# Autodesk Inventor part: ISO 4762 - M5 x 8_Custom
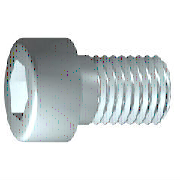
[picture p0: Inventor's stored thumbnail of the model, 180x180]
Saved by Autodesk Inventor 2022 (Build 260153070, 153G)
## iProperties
IsCustomPart: 0
Created: 2021-02
Part Number: ISO 4762 - M5 x 8_Custom
Material: Acier inoxydable 440C
Description: Vis cylindrique à six pans creux
Document SubType Name: Modeling
Standard: ISO 4762
Designer: Fabian
Standard Revision: Fourth edition 2004-03-01
Standards Organization: ISO
Language: fr-FR
Size Designation: M5 x 8
Categories: <MemberInstance><Categories><Category DisplayName="Visserie" InternalName="e4da775c-781d-43d5-af7c-5136215cf5a6" Mnemonic="FSTN"><Category DisplayName="Vis" Int
Density: 7.75 g/cm^3
Appearance: Semi-poli
Author: Fabian
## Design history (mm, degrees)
sketch "Esquisse1"
  geometry: L1 (-1.167, 0)-(8, 0); L2 (8, 0)-(8, 2.5); L3 (8, 2.5)-(2, 2.5); L4 (2, 2.5)-(1.509, 2.5); L5 (1.509, 2.5)-(0, 2.5); L6 (0, 2.5)-(0, 4.25); L7 (0, 4.25)-(-5, 4.25); L8 (-5, 4.25)-(-5, 2.309); L9 (-5, 2.309)-(-2.5, 2.309); L10 (-2.5, 2.309)-(-1.167, 0); L11 (-7.6, 0)-(10.6, 0) reference; L12 (0, -0.85)-(0, 5.1) reference; L13 (2, 2.5)-(0, 2.5)
  constraints: 22 end point, 6 parallel, 2 collinear, 2 perpendicular, 1 horizontal, 1 point on line
  dimensions: "d1" = 6 distance from line of L3.end L2 (= GEL); "d2" = 0.49086 distance of L4.end L3.end (computed from GAL); "d3" = 5 distance between parallel lines of L8 L6 (= KOH); "d4" = 2.5 distance of L8.end L9.end (= INTI); "d5" = 60 deg angle of L10 L1; "d6" = 5 diameter of L3 L1 (= GD); "d7" = 5 diameter of L5 L1 (= BDM); "d8" = 4.6188 diameter of L9 L1 (= 1.1547 x SW); "d9" = 8.5 diameter of L7 L1 (= KOD); "d26" = 8 distance between parallel lines of L12 L2 (= NLG)
revolve "Corps" sketch "Esquisse1" stored, may be unused: angle "d10" = 90 deg
sketch "Esquisse2"
  geometry: L1 (0, -5.95)-(0, 5.95) reference; L2 (-5.95, 0)-(5.95, 0) reference; L3 (2.309, 0)-(1.155, -2); L4 (1.155, -2)-(-1.155, -2); L5 (-1.155, -2)-(-2.309, 0); L6 (-2.309, 0)-(-1.155, 2); L7 (-1.155, 2)-(1.155, 2); L8 (1.155, 2)-(2.309, 0); 2 further points
  constraints: 12 end point, 1 coincident, 1 horizontal alignment, 1 point on line, 12 other
extrude "Rainure" join sketch "Esquisse2" stored distance "d11" = 10; taper "d12" = 0 deg
workplane "Work Plane1"
fillet "Fillet2" dims "d30" = 0.1 (= R)
body "Solid1"
fillet "Congé1" dims "d17" = 0.5 (= RR)
feature "Filetage" dims "d13" = 6 (= GEL), "d14" = 0
chamfer "Chanfrein1" distance "d15" = 0.49076 (= -0.5 x SPD + 0.5 x GD); stored, may be unused: second distance "d16" = 0.49076 (= GUL), angle "d27" = 45 deg
other parameters: "GD" = 5 [user parameter; used in 2 equation terms], "NLG" = 8 [user parameter; used in 1 equation term], "GEL" = 6 [user parameter; used in 2 equation terms], "KOD" = 8.5 [user parameter; used in 1 equation term], "KOH" = 5 [user parameter; used in 1 equation term], "INTI" = 2.5 [user parameter; used in 1 equation term], "GAL" = 0.49076 (= 0.61345 x PTC) [user parameter; used in 1 equation term], "GUL" = 0.49076 (= 0.61345 x PTC) [user parameter; used in 1 equation term], "BDM" = 5 (= NND) [user parameter; used in 1 equation term], "SW" = 4 [user parameter; used in 2 equation terms], "RR" = 0.5 [user parameter; used in 1 equation term], "SPD" = 4.01848 (= NND - 1.2269 x PTC) [user parameter; used in 1 equation term], "d19" = 0, "d28" = 0, "d29" = 0, "R" = 0.1 [user parameter; used in 1 equation term], "TOA" = 30 deg [user parameter], "GD1" = 4.01848 (= THREADDIA - 1.2269 x PTC) [user parameter], "THREADDIA" = 5 [user parameter; used in 1 equation term], "FAWI" = 45 deg [user parameter], "TPU" = 12.5 (computed from PTC) [user parameter], "PTC" = 0.8 [user parameter; used in 5 equation terms], "NND" = 5 [user parameter; used in 2 equation terms], "E0" = 4.62 (= 1.155 x SW) [user parameter]
